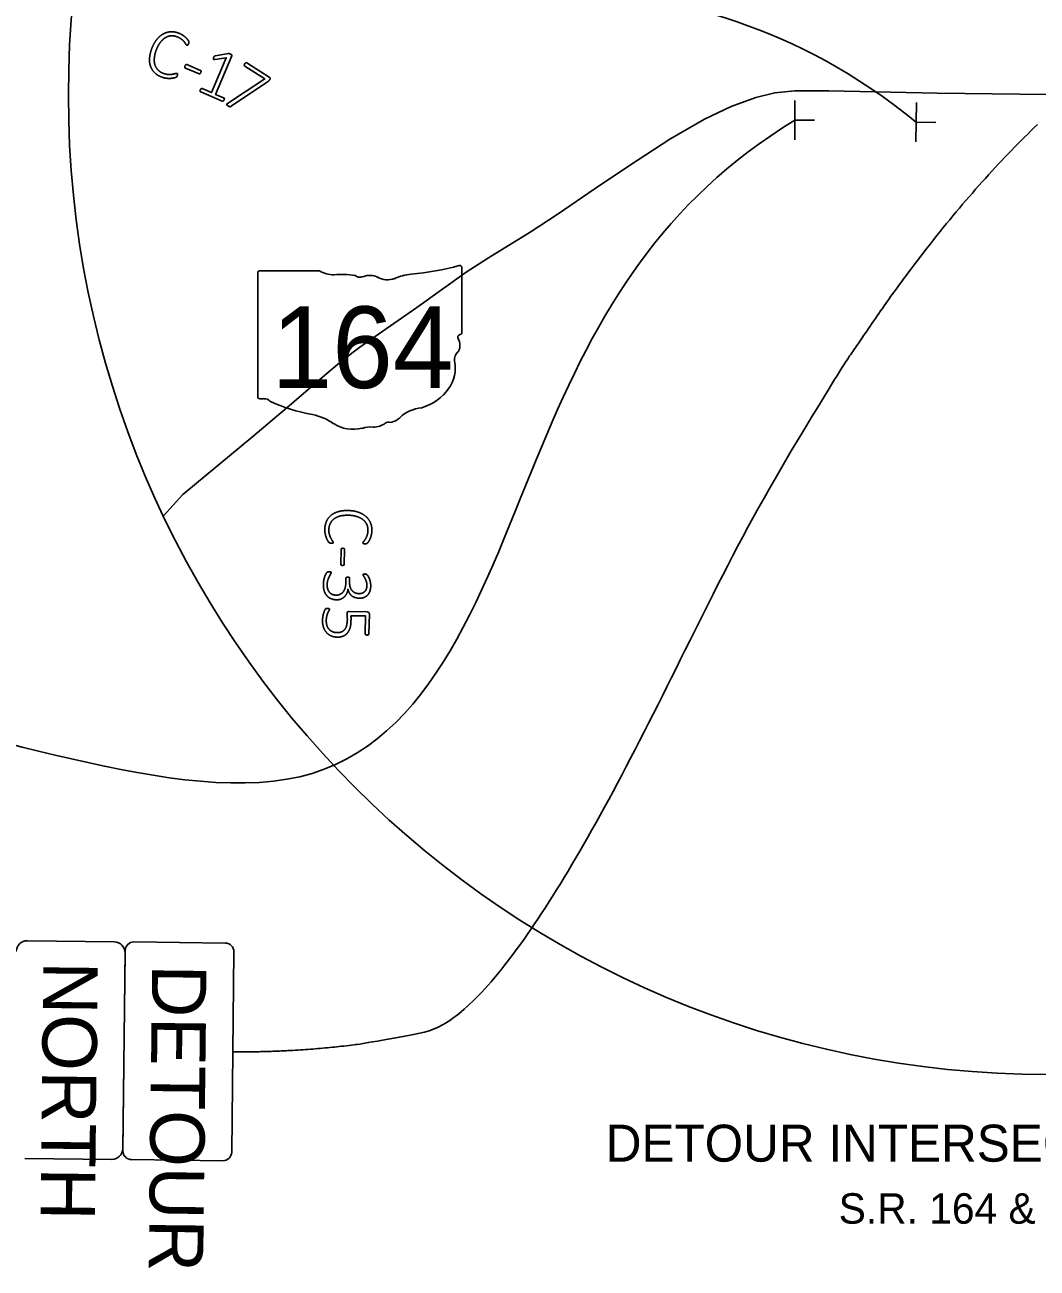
# Model space of a CAD drawing. Extents: x -202 to 1556, y 0 to 676.
# Drawn here: x 96 to 189, y 220.4 to 334.7 of the extents above; entities that cross this region are included whole.
import ezdxf

# ---------------------------------------------------------------- set-up
doc = ezdxf.new("R2010")
doc.units = 0
for name, color, linetype in [('Default', 7, 'Continuous'), ('GM_X_City_Street', 7, 'Continuous'), ('GM_X_Minor_Lake', 7, 'Continuous'), ('GM_X_Minor_River_Text', 7, 'Continuous'), ('GM_X_State_Location', 7, 'Continuous'), ('SH_Data', 7, 'Continuous')]:
    doc.layers.add(name, color=color, linetype=linetype)

msp = doc.modelspace()

# ---------------------------------------------------------------- linework, layer by layer
at = {"layer": 'Default'}
msp.add_lwpolyline([(108.73, 289.55), (110.53, 291.51), (116.95, 296.85), (120.51, 299.84), (123.56, 302.49), (125.3, 303.91), (126.78, 305.05), (132.02, 308.69), (136.57, 311.94), (138.62, 313.28), (142.45, 315.64), (145.01, 317.3), (148.41, 319.63), (151.57, 321.75), (155.29, 324.17), (158.48, 326.01), (160.91, 327.18), (163.19, 328.01), (164.92, 328.44), (166.78, 328.62), (169.88, 328.61), (179.85, 328.39), (189.95, 328.28)], dxfattribs=at)
at = {"layer": 'GM_X_City_Street'}
for p, q in [((123.08, 312.08), (117.59, 312.08)), ((136.15, 306.41), (136.15, 312.36)), ((117.41, 311.88), (117.41, 300.5)), ((136.15, 306.41), (136.15, 306.41))]:
    msp.add_line(p, q, dxfattribs=at)
for centre, major_axis, start_param, end_param in [((117.62, 311.91), (0.217, 0), 1.712693, 3.28349), ((124.39, 313.4), (2.11, 0), 4.042523, 4.731795), ((129.48, 327.6), (19.88, 0), 4.814394, 5.042369), ((135.95, 312.39), (0.209, 0), 6.141152, 7.989035), ((125.09, 305.69), (7.56, 0), 1.404758, 1.657858), ((126.8, 311.97), (0.608, 0), 3.836095, 5.185415), ((127.7, 310.65), (1.26, 0), 0.950623, 2.079405), ((129.33, 312.46), (1.52, 0), 4.081561, 5.145723), ((132.01, 308.6), (4, 0), 1.699011, 2.107814), ((135.93, 306.38), (0.223, 0), 5.05454, 6.418171), ((136.11, 305.97), (0.323, 0), 1.883978, 3.671073), ((134.05, 305.22), (1.94, 0), 5.934695, 6.695948), ((136.9, 303.91), (1.41, 0), 2.387724, 3.262537), ((130.59, 303.16), (4.97, 0), 5.101752, 6.440018), ((117.62, 300.47), (0.219, 0), 3.00124, 4.508301), ((117.66, 301.64), (1.67, 0), 4.665946, 4.897461), ((118, 299.84), (0.603, 0), 0.519207, 1.627899), ((125.61, 310.07), (14.36, 0), 4.195997, 4.488961), ((132.69, 297.3), (2.72, 0), 1.647645, 2.488434), ((121.33, 295.38), (4.49, 0), 0.823519, 1.323587), ((129.24, 299.4), (1.61, 0), 4.937069, 5.64225), ((126.19, 299.79), (2.85, 0), 4.026481, 4.996735), ((127.84, 295.85), (2.34, 0), 1.495662, 1.94098), ((128.04, 298.93), (1.52, 0), 4.691044, 5.507374), ((129.42, 297.83), (0.428, 0), 1.147584, 2.315152)]:
    msp.add_ellipse(centre, major_axis=major_axis, ratio=0.8, start_param=start_param, end_param=end_param, dxfattribs=at)
at = {"layer": 'GM_X_Minor_Lake'}
for p, q in [((166.76, 324.12), (166.77, 327.72)), ((177.9, 323.93), (177.94, 327.53)), ((166.77, 325.92), (168.57, 325.92)), ((177.92, 325.73), (179.72, 325.71)), ((96.23, 250.49), (104.22, 250.41)), ((105.21, 249.39), (105.01, 231.4)), ((104, 230.41), (96, 230.5))]:
    msp.add_line(p, q, dxfattribs=at)
for points in [[(114.42, 250.29), (106.02, 250.39)], [(105.22, 249.59), (105.01, 231.2)], [(115.01, 231.08), (115.22, 249.48)], [(105.8, 230.39), (114.2, 230.29)]]:
    msp.add_lwpolyline(points, dxfattribs=at)
for centre, radius, start, end in [((96.21, 249.5), 1, 89.359, 179.359), ((104.21, 249.41), 1, 359.359, 89.359), ((106.02, 249.59), 0.8, 89.359, 179.359), ((114.42, 249.49), 0.8, 359.359, 89.359), ((104.01, 231.41), 1, 269.359, 359.359), ((105.81, 231.19), 0.8, 179.359, 269.359), ((114.21, 231.09), 0.8, 269.359, 359.359)]:
    msp.add_arc(centre, radius, start, end, dxfattribs=at)
at = {"layer": 'GM_X_State_Location'}
for p, q in [((113.51, 331.83), (114.69, 332.04)), ((112.02, 330.19), (110.75, 330.71)), ((110.88, 331.02), (112.15, 330.49)), ((112.17, 330.3), (112.17, 330.3)), ((116.41, 331.18), (118.47, 329.86)), ((110.01, 330.02), (110.01, 330.02)), ((118.29, 329.43), (114.96, 327.2)), ((118.5, 329.63), (118.5, 329.63)), ((114.14, 327.67), (112.16, 328.51)), ((114.31, 327.78), (114.31, 327.78)), ((124.16, 287.03), (124.16, 287.03)), ((125.03, 285.1), (125.07, 286.47)), ((125.39, 286.47), (125.36, 285.09)), ((125.19, 285), (125.19, 285)), ((125.5, 283.39), (125.51, 283.81)), ((125.85, 283.8), (125.85, 283.43)), ((125.71, 282.83), (125.7, 282.83)), ((124.65, 281.84), (124.65, 281.84)), ((125.81, 280.76), (127.48, 280.72)), ((127.67, 280.52), (127.63, 278.72)), ((124.73, 278.4), (124.73, 278.4))]:
    msp.add_line(p, q, dxfattribs=at)
for points in [[(112.29, 328.82), (113.16, 328.45), (114.51, 331.66), (113.47, 331.5)], [(115.02, 331.84), (113.53, 328.29), (114.27, 327.98)], [(114.62, 327.45), (118.05, 329.71), (116.22, 330.88)], [(127.27, 278.73), (127.31, 280.35), (125.96, 280.38)]]:
    msp.add_lwpolyline(points, dxfattribs=at)
for points in [[(108.09, 333.29), (108.35, 333.63), (108.68, 333.82)], [(108.68, 333.82), (109, 334.01), (109.36, 334.04)], [(109.41, 333.67), (109.13, 333.64), (108.88, 333.48)], [(109.36, 334.04), (109.73, 334.07), (110.1, 333.93)], [(109.96, 333.59), (109.68, 333.7), (109.41, 333.67)], [(110.1, 333.93), (110.28, 333.87), (110.44, 333.77)], [(110.44, 333.77), (110.6, 333.68), (110.72, 333.57)], [(107.65, 332.46), (107.83, 332.94), (108.09, 333.29)], [(108.43, 333.04), (108.22, 332.75), (108.07, 332.34)], [(108.88, 333.48), (108.64, 333.32), (108.43, 333.04)], [(110.38, 333.37), (110.22, 333.5), (109.96, 333.59)], [(110.64, 333.12), (110.54, 333.24), (110.38, 333.37)], [(110.8, 332.9), (110.74, 333), (110.64, 333.12)], [(110.72, 333.57), (110.84, 333.47), (110.93, 333.36)], [(110.9, 332.8), (110.85, 332.81), (110.8, 332.9)], [(110.94, 332.8), (110.92, 332.79), (110.9, 332.8)], [(110.93, 333.36), (111.02, 333.25), (111.04, 333.2)], [(110.98, 332.82), (110.96, 332.8), (110.94, 332.8)], [(111.01, 332.87), (111, 332.84), (110.98, 332.82)], [(111.05, 332.95), (111.03, 332.9), (111.01, 332.87)], [(111.04, 333.2), (111.07, 333.14), (111.07, 333.12)], [(111.07, 333.01), (111.06, 332.98), (111.05, 332.95)], [(111.07, 333.12), (111.08, 333.09), (111.08, 333.07)], [(111.08, 333.07), (111.07, 333.04), (111.07, 333.01)], [(107.46, 331.57), (107.48, 331.98), (107.65, 332.46)], [(107.57, 330.83), (107.44, 331.16), (107.46, 331.57)], [(107.9, 331.6), (107.87, 331.26), (107.96, 330.99)], [(108.07, 332.34), (107.92, 331.94), (107.9, 331.6)], [(113.33, 331.53), (113.32, 331.56), (113.33, 331.59)], [(113.33, 331.59), (113.33, 331.63), (113.36, 331.68)], [(113.37, 331.5), (113.34, 331.51), (113.33, 331.53)], [(113.36, 331.68), (113.37, 331.72), (113.39, 331.74)], [(113.47, 331.5), (113.41, 331.49), (113.37, 331.5)], [(113.39, 331.74), (113.4, 331.77), (113.42, 331.79)], [(113.42, 331.79), (113.44, 331.81), (113.46, 331.82)], [(113.46, 331.82), (113.48, 331.83), (113.51, 331.83)], [(114.69, 332.04), (114.7, 332.04), (114.72, 332.04)], [(114.72, 332.04), (114.74, 332.04), (114.76, 332.03)], [(114.76, 332.03), (114.79, 332.03), (114.81, 332.02)], [(114.81, 332.02), (114.84, 332.01), (114.87, 332)], [(114.87, 332), (114.92, 331.98), (114.95, 331.96)], [(114.95, 331.96), (114.99, 331.94), (115.01, 331.92)], [(115.01, 331.92), (115.02, 331.9), (115.03, 331.88)], [(115.03, 331.88), (115.03, 331.86), (115.02, 331.84)], [(107.95, 330.26), (107.69, 330.5), (107.57, 330.83)], [(108.58, 329.88), (108.2, 330.01), (107.95, 330.26)], [(107.96, 330.99), (108.05, 330.72), (108.25, 330.52)], [(108.25, 330.52), (108.45, 330.32), (108.75, 330.21)], [(109.85, 330.2), (109.96, 330.23), (110, 330.22)], [(110, 330.22), (110.02, 330.21), (110.03, 330.2)], [(110.7, 330.77), (110.69, 330.82), (110.72, 330.9)], [(110.75, 330.71), (110.71, 330.73), (110.7, 330.77)], [(110.72, 330.9), (110.76, 330.99), (110.8, 331.01)], [(110.8, 331.01), (110.84, 331.03), (110.88, 331.02)], [(112.17, 330.3), (112.13, 330.22), (112.1, 330.19)], [(112.15, 330.49), (112.16, 330.48), (112.18, 330.47)], [(112.19, 330.38), (112.19, 330.35), (112.17, 330.3)], [(112.18, 330.47), (112.19, 330.45), (112.2, 330.43)], [(112.2, 330.43), (112.2, 330.41), (112.19, 330.38)], [(116.17, 330.98), (116.17, 331.04), (116.21, 331.1)], [(116.22, 330.88), (116.17, 330.91), (116.17, 330.98)], [(116.21, 331.1), (116.24, 331.14), (116.26, 331.16)], [(116.26, 331.16), (116.29, 331.18), (116.31, 331.19)], [(116.31, 331.19), (116.34, 331.2), (116.36, 331.2)], [(116.36, 331.2), (116.39, 331.2), (116.41, 331.18)], [(109.02, 329.77), (108.81, 329.79), (108.58, 329.88)], [(108.75, 330.21), (109, 330.12), (109.21, 330.12)], [(109.41, 329.76), (109.24, 329.75), (109.02, 329.77)], [(109.21, 330.12), (109.42, 330.11), (109.58, 330.14)], [(109.7, 329.8), (109.58, 329.77), (109.41, 329.76)], [(109.58, 330.14), (109.74, 330.17), (109.85, 330.2)], [(109.87, 329.85), (109.83, 329.83), (109.7, 329.8)], [(109.92, 329.88), (109.91, 329.87), (109.87, 329.85)], [(109.96, 329.91), (109.94, 329.9), (109.92, 329.88)], [(109.98, 329.96), (109.97, 329.93), (109.96, 329.91)], [(110.01, 330.02), (110, 329.99), (109.98, 329.96)], [(110.03, 330.11), (110.03, 330.07), (110.01, 330.02)], [(110.03, 330.2), (110.04, 330.19), (110.04, 330.16)], [(110.04, 330.16), (110.04, 330.14), (110.03, 330.11)], [(112.1, 330.19), (112.06, 330.17), (112.02, 330.19)], [(118.36, 329.47), (118.33, 329.45), (118.29, 329.43)], [(118.41, 329.52), (118.39, 329.5), (118.36, 329.47)], [(118.46, 329.57), (118.43, 329.55), (118.41, 329.52)], [(118.5, 329.63), (118.48, 329.6), (118.46, 329.57)], [(118.47, 329.86), (118.5, 329.84), (118.52, 329.82)], [(118.53, 329.7), (118.52, 329.67), (118.5, 329.63)], [(118.52, 329.82), (118.54, 329.79), (118.54, 329.76)], [(118.54, 329.76), (118.55, 329.74), (118.53, 329.7)], [(112.11, 328.57), (112.1, 328.59), (112.11, 328.62)], [(112.11, 328.62), (112.11, 328.66), (112.13, 328.7)], [(112.13, 328.53), (112.12, 328.54), (112.11, 328.57)], [(112.13, 328.7), (112.14, 328.74), (112.16, 328.76)], [(112.16, 328.51), (112.14, 328.51), (112.13, 328.53)], [(112.16, 328.76), (112.18, 328.79), (112.2, 328.8)], [(112.2, 328.8), (112.23, 328.82), (112.25, 328.82)], [(112.25, 328.82), (112.27, 328.82), (112.29, 328.82)], [(114.27, 327.98), (114.3, 327.97), (114.31, 327.96)], [(114.31, 327.96), (114.33, 327.94), (114.33, 327.91)], [(114.18, 327.67), (114.16, 327.67), (114.14, 327.67)], [(114.23, 327.68), (114.21, 327.67), (114.18, 327.67)], [(114.27, 327.71), (114.25, 327.69), (114.23, 327.68)], [(114.31, 327.78), (114.29, 327.74), (114.27, 327.71)], [(114.33, 327.85), (114.33, 327.82), (114.31, 327.78)], [(114.33, 327.91), (114.34, 327.89), (114.33, 327.85)], [(114.55, 327.36), (114.55, 327.39), (114.57, 327.41)], [(114.58, 327.3), (114.55, 327.33), (114.55, 327.36)], [(114.57, 327.41), (114.58, 327.42), (114.62, 327.45)], [(114.68, 327.23), (114.61, 327.27), (114.58, 327.3)], [(114.77, 327.18), (114.73, 327.2), (114.68, 327.23)], [(114.84, 327.16), (114.81, 327.16), (114.77, 327.18)], [(114.9, 327.16), (114.87, 327.15), (114.84, 327.16)], [(114.96, 327.2), (114.93, 327.17), (114.9, 327.16)], [(123.73, 289.06), (123.87, 289.39), (124.15, 289.61)], [(124.43, 289.28), (124.2, 289.12), (124.07, 288.86)], [(124.15, 289.61), (124.42, 289.83), (124.82, 289.94)], [(124.98, 289.54), (124.65, 289.45), (124.43, 289.28)], [(124.82, 289.94), (125.21, 290.06), (125.72, 290.04)], [(125.74, 289.61), (125.31, 289.62), (124.98, 289.54)], [(125.72, 290.04), (126.24, 290.03), (126.65, 289.89)], [(126.52, 289.49), (126.18, 289.6), (125.74, 289.61)], [(127.08, 289.2), (126.86, 289.38), (126.52, 289.49)], [(126.65, 289.89), (127.05, 289.75), (127.34, 289.5)], [(127.43, 288.76), (127.31, 289.02), (127.08, 289.2)], [(127.34, 289.5), (127.62, 289.26), (127.76, 288.92)], [(123.57, 288.34), (123.58, 288.74), (123.73, 289.06)], [(123.61, 287.89), (123.56, 288.09), (123.57, 288.34)], [(124.07, 288.86), (123.95, 288.61), (123.94, 288.29)], [(123.94, 288.29), (123.93, 288.02), (124, 287.82)], [(127.53, 288.21), (127.54, 288.51), (127.43, 288.76)], [(127.45, 287.75), (127.53, 287.94), (127.53, 288.21)], [(127.76, 288.92), (127.91, 288.59), (127.9, 288.18)], [(127.9, 288.18), (127.89, 287.99), (127.85, 287.82)], [(123.72, 287.52), (123.65, 287.68), (123.61, 287.89)], [(123.85, 287.25), (123.78, 287.36), (123.72, 287.52)], [(123.95, 287.11), (123.92, 287.15), (123.85, 287.25)], [(124, 287.07), (123.98, 287.08), (123.95, 287.11)], [(124, 287.82), (124.06, 287.62), (124.14, 287.48)], [(124.04, 287.05), (124.02, 287.06), (124, 287.07)], [(124.09, 287.04), (124.06, 287.04), (124.04, 287.05)], [(124.16, 287.03), (124.12, 287.04), (124.09, 287.04)], [(124.14, 287.48), (124.22, 287.33), (124.28, 287.24)], [(124.25, 287.04), (124.21, 287.03), (124.16, 287.03)], [(124.31, 287.05), (124.28, 287.04), (124.25, 287.04)], [(124.28, 287.24), (124.35, 287.15), (124.34, 287.1)], [(124.34, 287.07), (124.33, 287.06), (124.31, 287.05)], [(124.34, 287.1), (124.34, 287.08), (124.34, 287.07)], [(127.07, 287.07), (127.07, 287.12), (127.14, 287.2)], [(127.09, 287.03), (127.07, 287.05), (127.07, 287.07)], [(127.12, 287), (127.1, 287.02), (127.09, 287.03)], [(127.18, 286.99), (127.15, 286.99), (127.12, 287)], [(127.14, 287.2), (127.21, 287.28), (127.3, 287.42)], [(127.26, 286.98), (127.22, 286.98), (127.18, 286.99)], [(127.33, 286.98), (127.3, 286.98), (127.26, 286.98)], [(127.3, 287.42), (127.38, 287.55), (127.45, 287.75)], [(127.39, 286.99), (127.36, 286.98), (127.33, 286.98)], [(127.43, 287.01), (127.41, 287), (127.39, 286.99)], [(127.5, 287.06), (127.45, 287.02), (127.43, 287.01)], [(127.62, 287.22), (127.54, 287.1), (127.5, 287.06)], [(127.75, 287.49), (127.69, 287.34), (127.62, 287.22)], [(127.85, 287.82), (127.81, 287.64), (127.75, 287.49)], [(125.07, 286.47), (125.07, 286.52), (125.1, 286.54)], [(125.1, 286.54), (125.14, 286.57), (125.23, 286.57)], [(125.23, 286.57), (125.32, 286.57), (125.36, 286.54)], [(125.36, 286.54), (125.39, 286.51), (125.39, 286.47)], [(125.07, 285.03), (125.03, 285.06), (125.03, 285.1)], [(125.19, 285), (125.1, 285), (125.07, 285.03)], [(125.27, 285.01), (125.24, 285), (125.19, 285)], [(125.32, 285.02), (125.3, 285.01), (125.27, 285.01)], [(125.35, 285.05), (125.34, 285.04), (125.32, 285.02)], [(125.36, 285.09), (125.36, 285.07), (125.35, 285.05)], [(123.44, 283.28), (123.44, 283.49), (123.48, 283.67)], [(123.48, 283.67), (123.52, 283.85), (123.57, 284)], [(123.57, 284), (123.63, 284.14), (123.68, 284.23)], [(123.68, 284.23), (123.74, 284.32), (123.76, 284.35)], [(123.76, 284.35), (123.78, 284.37), (123.8, 284.38)], [(123.85, 283.65), (123.79, 283.47), (123.78, 283.24)], [(123.8, 284.38), (123.82, 284.39), (123.84, 284.4)], [(123.84, 284.4), (123.87, 284.41), (123.9, 284.41)], [(123.98, 283.98), (123.91, 283.84), (123.85, 283.65)], [(123.9, 284.41), (123.94, 284.41), (123.99, 284.41)], [(124.1, 284.21), (124.05, 284.12), (123.98, 283.98)], [(123.99, 284.41), (124.09, 284.41), (124.13, 284.39)], [(124.16, 284.33), (124.16, 284.3), (124.1, 284.21)], [(124.13, 284.39), (124.16, 284.37), (124.16, 284.33)], [(125.43, 282.91), (125.49, 283.12), (125.5, 283.39)], [(125.51, 283.81), (125.51, 283.83), (125.52, 283.85)], [(125.52, 283.85), (125.53, 283.87), (125.55, 283.89)], [(125.55, 283.89), (125.57, 283.9), (125.61, 283.91)], [(125.61, 283.91), (125.64, 283.93), (125.69, 283.92)], [(125.69, 283.92), (125.73, 283.92), (125.76, 283.91)], [(125.76, 283.91), (125.79, 283.9), (125.82, 283.88)], [(125.82, 283.88), (125.84, 283.87), (125.85, 283.85)], [(125.85, 283.43), (125.84, 283.2), (125.9, 283.01)], [(125.85, 283.85), (125.85, 283.82), (125.85, 283.8)], [(127.09, 284.16), (127.1, 284.18), (127.12, 284.19)], [(127.09, 284.13), (127.09, 284.15), (127.09, 284.16)], [(127.14, 284.01), (127.09, 284.09), (127.09, 284.13)], [(127.12, 284.19), (127.14, 284.2), (127.18, 284.2)], [(127.27, 283.8), (127.2, 283.93), (127.14, 284.01)], [(127.18, 284.2), (127.21, 284.21), (127.27, 284.21)], [(127.27, 284.21), (127.3, 284.21), (127.33, 284.2)], [(127.39, 283.51), (127.33, 283.67), (127.27, 283.8)], [(127.33, 284.2), (127.36, 284.2), (127.38, 284.19)], [(127.38, 284.19), (127.4, 284.18), (127.42, 284.16)], [(127.44, 283.14), (127.44, 283.34), (127.39, 283.51)], [(127.42, 284.16), (127.44, 284.15), (127.47, 284.12)], [(127.47, 284.12), (127.5, 284.09), (127.56, 284)], [(127.56, 284), (127.62, 283.9), (127.67, 283.77)], [(127.67, 283.77), (127.72, 283.63), (127.76, 283.46)], [(127.76, 283.46), (127.79, 283.29), (127.79, 283.1)], [(123.51, 282.66), (123.43, 282.93), (123.44, 283.28)], [(123.76, 282.21), (123.6, 282.4), (123.51, 282.66)], [(123.78, 283.24), (123.78, 283), (123.84, 282.82)], [(123.84, 282.82), (123.89, 282.65), (124, 282.52)], [(124, 282.52), (124.11, 282.4), (124.27, 282.33)], [(124.27, 282.33), (124.42, 282.27), (124.61, 282.27)], [(124.61, 282.27), (124.8, 282.26), (124.96, 282.34)], [(124.96, 282.34), (125.12, 282.41), (125.24, 282.55)], [(125.24, 282.55), (125.36, 282.7), (125.43, 282.91)], [(125.59, 282.43), (125.5, 282.24), (125.36, 282.11)], [(125.7, 282.83), (125.67, 282.61), (125.59, 282.43)], [(125.82, 282.47), (125.73, 282.63), (125.71, 282.83)], [(126.04, 282.21), (125.91, 282.32), (125.82, 282.47)], [(125.9, 283.01), (125.96, 282.82), (126.07, 282.69)], [(126.07, 282.69), (126.18, 282.56), (126.34, 282.48)], [(126.34, 282.48), (126.5, 282.41), (126.7, 282.4)], [(126.7, 282.4), (126.85, 282.4), (126.98, 282.44)], [(126.98, 282.44), (127.12, 282.49), (127.22, 282.58)], [(127.47, 282.24), (127.33, 282.11), (127.14, 282.04)], [(127.22, 282.58), (127.32, 282.67), (127.38, 282.81)], [(127.38, 282.81), (127.43, 282.95), (127.44, 283.14)], [(127.7, 282.59), (127.61, 282.38), (127.47, 282.24)], [(127.79, 283.1), (127.78, 282.81), (127.7, 282.59)], [(124.15, 281.94), (123.92, 282.03), (123.76, 282.21)], [(124.65, 281.84), (124.38, 281.84), (124.15, 281.94)], [(125.04, 281.9), (124.86, 281.83), (124.65, 281.84)], [(125.36, 282.11), (125.22, 281.98), (125.04, 281.9)], [(126.35, 282.05), (126.18, 282.1), (126.04, 282.21)], [(126.73, 281.98), (126.53, 281.99), (126.35, 282.05)], [(127.14, 282.04), (126.95, 281.98), (126.73, 281.98)], [(123.36, 279.98), (123.36, 280.17), (123.4, 280.35)], [(123.44, 279.35), (123.35, 279.63), (123.36, 279.98)], [(123.4, 280.35), (123.43, 280.52), (123.48, 280.66)], [(123.48, 280.66), (123.52, 280.8), (123.56, 280.88)], [(123.56, 280.88), (123.61, 280.97), (123.63, 280.99)], [(123.63, 280.99), (123.65, 281.02), (123.67, 281.02)], [(123.67, 281.02), (123.68, 281.03), (123.7, 281.04)], [(123.7, 281.04), (123.72, 281.04), (123.75, 281.05)], [(123.76, 280.37), (123.71, 280.19), (123.7, 279.94)], [(123.7, 279.94), (123.7, 279.71), (123.75, 279.51)], [(123.75, 281.05), (123.79, 281.05), (123.83, 281.05)], [(123.86, 280.67), (123.8, 280.55), (123.76, 280.37)], [(123.83, 281.05), (123.87, 281.05), (123.9, 281.04)], [(123.96, 280.86), (123.91, 280.79), (123.86, 280.67)], [(123.9, 281.04), (123.93, 281.03), (123.96, 281.02)], [(123.96, 281.02), (123.98, 281.01), (123.99, 280.99)], [(124, 280.96), (124, 280.92), (123.96, 280.86)], [(123.99, 280.99), (124, 280.98), (124, 280.96)], [(125.57, 279.47), (125.63, 279.69), (125.64, 279.99)], [(125.61, 280.6), (125.61, 280.68), (125.65, 280.72)], [(125.63, 280.34), (125.61, 280.48), (125.61, 280.6)], [(125.64, 279.99), (125.64, 280.2), (125.63, 280.34)], [(125.65, 280.72), (125.7, 280.76), (125.81, 280.76)], [(125.96, 280.38), (125.98, 280.26), (125.98, 280.14)], [(125.98, 280.14), (125.98, 280.02), (125.97, 279.85)], [(127.48, 280.72), (127.57, 280.71), (127.62, 280.66)], [(127.62, 280.66), (127.67, 280.61), (127.67, 280.52)], [(123.7, 278.86), (123.52, 279.06), (123.44, 279.35)], [(124.13, 278.53), (123.87, 278.65), (123.7, 278.86)], [(123.75, 279.51), (123.8, 279.31), (123.93, 279.16)], [(123.93, 279.16), (124.05, 279.01), (124.24, 278.92)], [(124.24, 278.92), (124.43, 278.83), (124.7, 278.82)], [(124.7, 278.82), (124.93, 278.82), (125.1, 278.89)], [(125.1, 278.89), (125.27, 278.96), (125.39, 279.1)], [(125.39, 279.1), (125.51, 279.24), (125.57, 279.47)], [(125.87, 279.2), (125.77, 278.92), (125.6, 278.74)], [(125.97, 279.85), (125.96, 279.47), (125.87, 279.2)], [(124.73, 278.4), (124.39, 278.41), (124.13, 278.53)], [(125.21, 278.48), (124.99, 278.4), (124.73, 278.4)], [(125.6, 278.74), (125.44, 278.57), (125.21, 278.48)], [(127.32, 278.64), (127.27, 278.67), (127.27, 278.73)], [(127.45, 278.6), (127.37, 278.6), (127.32, 278.64)], [(127.52, 278.61), (127.49, 278.6), (127.45, 278.6)], [(127.58, 278.63), (127.55, 278.62), (127.52, 278.61)], [(127.61, 278.67), (127.6, 278.65), (127.58, 278.63)], [(127.63, 278.72), (127.63, 278.69), (127.61, 278.67)]]:
    msp.add_open_spline(points, degree=2, dxfattribs=at)
at = {"layer": 'SH_Data'}
msp.add_circle((190, 328.22), 90, dxfattribs=at)
for points, degree in [([(87.45, 355.18), (109.77, 345.09), (127.6, 339.7), (143.95, 339.31), (166.86, 334.83), (177.92, 325.73)], 3), ([(77.04, 271.97), (88.48, 271.69), (129.16, 253.62), (142.81, 298.28), (154.55, 318.45), (166.77, 325.92)], 3), ([(115.11, 240.28), (125.43, 240.28), (140.66, 244.18), (172.28, 309.41), (189.07, 325.53)], 2)]:
    msp.add_open_spline(points, degree=degree, dxfattribs=at)

# ---------------------------------------------------------------- texts
at = {"layer": 'GM_X_City_Street'}
msp.add_text('164', height=7.5, dxfattribs=at).set_placement((118.67, 301.3))
at = {"layer": 'GM_X_Minor_Lake'}
for s, p in [('NORTH', (97.7, 248.61)), ('DETOUR', (107.7, 248.33))]:
    msp.add_text(s, height=5, rotation=269.359, dxfattribs=at).set_placement(p)
at = {"layer": 'GM_X_Minor_River_Text'}
for s, height, p in [('DETOUR INTERSECTION DETAIL 1', 3.4, (149.39, 230.2)), ('S.R. 164 & S.R. 9', 2.8, (170.8, 224.5))]:
    msp.add_text(s, height=height, dxfattribs=at).set_placement(p)

doc.saveas('drawing.dxf')
